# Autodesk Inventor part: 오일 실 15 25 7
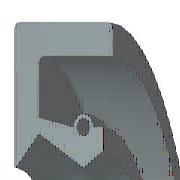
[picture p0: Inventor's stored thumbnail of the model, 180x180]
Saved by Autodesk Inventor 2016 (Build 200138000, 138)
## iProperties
Created: 2012-02
Part Number: 오일 실 15 25 7
Material: 고무
Description: 오일-실
Document SubType Name: Modeling
Standard: KS B 2804
Designer: mduedu
Standards Organization: KS
Language: ko-KR
Size Designation: D - 15 25 7
Categories: <MemberInstance><Categories><Category DisplayName="샤프트 부품" InternalName="7f7aeb1f-a693-4053-b835-cee3144e0d98" Mnemonic="SHFT"><Category DisplayName="실링" Intern
Density: 0.93 g/cm^3
Appearance: 고무 - 검은색 - 버전 1.1
IsCustomPart: 1
Author: mduedu
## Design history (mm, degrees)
revolve "본체" stored, may be unused: angle "d17" = 90 deg
revolve "스프링1" stored, may be unused: angle "d18" = 90 deg
body "Solid1"
sketch "스케치1"
  geometry: L1 (0, 12.5)-(7, 12.5); L2 (7, 10.75)-(1.75, 10.75); L3 (1.75, 9.25)-(4.9, 7.5); L4 (4.9, 7.5)-(0, 7.5); L5 (0, 0)-(9.586, 0) reference; L6 (4.9, 7.5)-(6.3, 8.375); L7 (0, 18)-(0, -3) reference; L8 (-1.941, 0)-(11.507, 0) reference; L9 (4.2, 9.6)-(1.75, 10.09); L10 (1.75, 10.09)-(1.75, 10.75); L11 (0, 12.5)-(0, 7.588); L12 (4.9, 7.5)-(0, 7.5); L13 (1.75, 9.25)-(0.152, 7.528); L14 (7, 12.5)-(7, 10.75); L15 (5.6, 9.6)-(6.3, 9.6); L16 (6.3, 9.6)-(6.3, 8.375); C1 r 0.455 at (4.9, 9.6); A1 r 0.7 centre (4.9, 9.6) between (5.6, 9.6) and (4.2, 9.6); A2 r 0.088 centre (0.088, 7.588) between (0, 7.588) and (0.152, 7.528); 1 further point
  constraints: 28 end point, 5 horizontal alignment, 5 point on line, 4 point on circle, 4 vertical alignment, 3 centre point, 3 tangent, 2 collinear, 2 horizontal, 2 perpendicular, 1 coincident, 1 parallel
  dimensions: "d0" = 25 diameter of L1 L5 (= SD2); "d1" = 1.75 distance of L1.end L2.start (= SD); "d2" = 0.91 diameter of C1 (= SPDI); "d3" = 1.4 diameter of A1 (= SPDA); "d4" = 15 diameter of L3.end L5 (= NND); "d5" = 18.5 diameter of L3.start L5 (= TKDM); "d7" = 20.18 diameter of L9.end L5 (= TKDM + 0.24 x SWDT); "d8" = 1.75 distance between parallel lines of L11 L10 (= SD); "d9" = 4.9 distance from line of L11 C1.centre (= SPDST); "d10" = 19.2 diameter of C1.centre L5 (= HLDM); "d11" = 0.0875 radius of A2 (= 0.25 x LAB); "d12" = 6.3 distance between parallel lines of L11 L16 (= SDI); "d13" = 16.75 diameter of L6.end L5 (= ABDM); "d14" = 7 distance from line of L11 L1.end (= SWDT)
fillet "모깎기1" dims "d6" = 0.3 (= RR)
other parameters: "SD2" = 25 [user parameter; used in 1 equation term], "SWDT" = 7 [user parameter; used in 2 equation terms], "RR" = 0.3 [user parameter; used in 1 equation term], "SD" = 1.75 [user parameter; used in 2 equation terms], "NND" = 15 [user parameter; used in 1 equation term], "SPDA" = 1.4 [user parameter; used in 1 equation term], "SPDI" = 0.91 [user parameter; used in 1 equation term], "TKDM" = 18.5 [user parameter; used in 2 equation terms], "HLDM" = 19.2 [user parameter; used in 1 equation term], "ABDM" = 16.75 [user parameter; used in 1 equation term], "SDI" = 6.3 [user parameter; used in 1 equation term], "SPDST" = 4.9 [user parameter; used in 1 equation term], "LAB" = 0.35 [user parameter; used in 1 equation term], "d15" = 0, "d16" = 0, "d19" = 0
